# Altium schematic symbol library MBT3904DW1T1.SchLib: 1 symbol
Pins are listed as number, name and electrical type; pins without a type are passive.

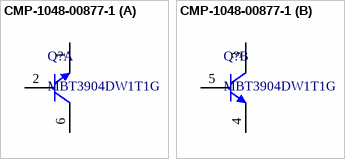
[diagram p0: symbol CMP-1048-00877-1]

## CMP-1048-00877-1
designator Q?, comment MBT3904DW1T1G
Dual General Purpose Transistors, 6-Pin SOT-363, Pb-Free, Tape and Reel; Manufacturer: On Semiconductor; Polarity: Dual NPN; fT Min (MHz): 300; IC Continuous (A): 0.2
footprint ONSC-SOT-363-6-419B-02_W_V (SOT23, 6-Leads, Body 2x1.25mm, Pitch 0.65mm)
part A pins: 1 E, 2 B, 6 C
part B pins: 3 C, 4 E, 5 B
